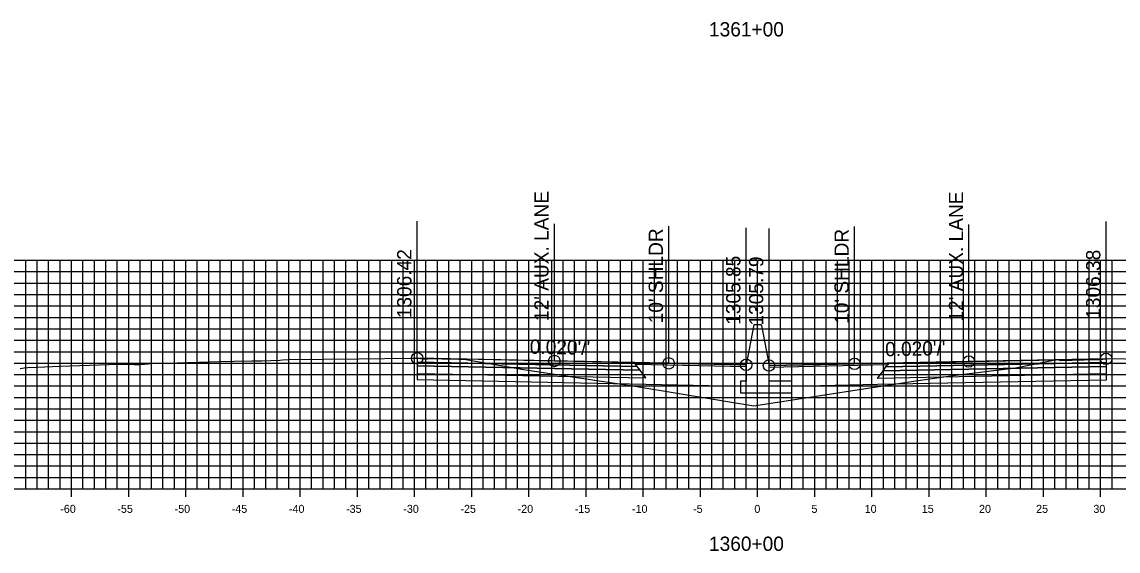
# Model space of a CAD drawing. Extents: x 674939 to 678919, y 750652 to 765176.
# Drawn here: x 678674.2 to 678770.1, y 753977.1 to 754023.4 of the extents above; entities that cross this region are included whole.
import ezdxf

# ---------------------------------------------------------------- set-up
doc = ezdxf.new("R2010")
doc.units = 0
for name, color, linetype in [('Level 10', 7, 'Continuous'), ('Level 17', 7, 'Continuous'), ('Level 18', 7, 'Continuous'), ('Level 19', 7, 'Continuous'), ('Level 20', 7, 'Continuous'), ('Level 22', 7, 'Continuous'), ('Level 23', 7, 'Continuous'), ('Level 4', 7, 'Continuous'), ('Level 8', 7, 'Continuous'), ('Level 9', 7, 'Continuous')]:
    doc.layers.add(name, color=color, linetype=linetype)

msp = doc.modelspace()

# ---------------------------------------------------------------- linework, layer by layer
at = {"layer": 'Level 10'}
msp.add_lwpolyline([(678674.048, 753993.082), (678674.392, 753993.137), (678674.701, 753993.177), (678675.43, 753993.209), (678676.214, 753993.236), (678677.547, 753993.284), (678681.802, 753993.422), (678682.901, 753993.454), (678683.995, 753993.442), (678684.544, 753993.442), (678684.738, 753993.453), (678684.916, 753993.47), (678685.224, 753993.499), (678685.501, 753993.514), (678687.776, 753993.582), (678691.544, 753993.697), (678692.721, 753993.721), (678694.301, 753993.748), (678695.165, 753993.763), (678696.744, 753993.803), (678696.98, 753993.832), (678697.466, 753993.867), (678703.662, 753993.928), (678708.193, 753993.977), (678708.761, 753993.972), (678708.783, 753993.972), (678708.944, 753993.971), (678709.066, 753993.953), (678709.302, 753993.937), (678709.666, 753993.938), (678710.152, 753993.94), (678710.937, 753993.931), (678712.395, 753993.886), (678713.023, 753993.859), (678716.762, 753993.212), (678718.065, 753992.991), (678720.408, 753992.641), (678727.622, 753991.562), (678731.844, 753990.867), (678738.197, 753989.808), (678747.411, 753991.235), (678752.377, 753992.004), (678755.648, 753992.452), (678761.101, 753993.139), (678764.554, 753993.825), (678764.78, 753993.867), (678764.858, 753993.826), (678764.862, 753993.824), (678765.055, 753993.766), (678765.09, 753993.767), (678767.021, 753993.84), (678767.062, 753993.841), (678767.082, 753993.841), (678768.435, 753993.875), (678768.476, 753993.877), (678769.007, 753993.925), (678769.012, 753993.926), (678769.014, 753993.926), (678769.255, 753993.948), (678773.508, 753993.866)], dxfattribs=at)
at = {"layer": 'Level 17'}
for points in [[(678738.203, 753996.896), (678737.533, 753993.396)], [(678738.863, 753996.836), (678738.863, 753996.896), (678738.203, 753996.896), (678738.203, 753996.896)], [(678738.863, 753996.836), (678739.533, 753993.336)], [(678737.533, 753993.396), (678737.533, 753991.961), (678737.033, 753991.961), (678737.033, 753990.961), (678741.533, 753990.961), (678741.533, 753991.961), (678739.533, 753991.961), (678739.533, 753993.336)]]:
    msp.add_lwpolyline(points, dxfattribs=at)
at = {"layer": 'Level 18'}
for points in [[(678737.533, 753993.396), (678730.761, 753993.532), (678720.761, 753993.732), (678708.761, 753993.972)], [(678769.012, 753993.926), (678757.012, 753993.686), (678747.012, 753993.486), (678739.533, 753993.336)]]:
    msp.add_lwpolyline(points, dxfattribs=at)
for points in [[(678708.761, 753993.972), (678708.761, 753993.642), (678728.011, 753993.257), (678727.761, 753993.592)], [(678769.012, 753993.926), (678769.012, 753993.596), (678749.762, 753993.211), (678750.012, 753993.546)], [(678727.761, 753993.592), (678737.533, 753993.396), (678737.537, 753993.239), (678727.88, 753993.432)], [(678749.893, 753993.386), (678739.533, 753993.179), (678739.533, 753993.336), (678750.012, 753993.546)]]:
    msp.add_lwpolyline(points, close=True, dxfattribs=at)
at = {"layer": 'Level 19'}
for points in [[(678708.761, 753993.642), (678708.761, 753993.312), (678728.261, 753992.922), (678728.011, 753993.257)], [(678769.012, 753993.596), (678769.012, 753993.266), (678749.512, 753992.876), (678749.762, 753993.211)], [(678708.761, 753993.312), (678708.761, 753992.652), (678728.761, 753992.252), (678728.261, 753992.922)], [(678769.012, 753993.266), (678769.012, 753992.606), (678749.012, 753992.206), (678749.512, 753992.876)]]:
    msp.add_lwpolyline(points, close=True, dxfattribs=at)
for points in [[(678708.761, 753992.652), (678708.761, 753992.112), (678728.761, 753991.712), (678737.033, 753991.546)], [(678769.012, 753992.606), (678769.012, 753992.066), (678749.012, 753991.666), (678741.533, 753991.516)]]:
    msp.add_lwpolyline(points, dxfattribs=at)
at = {"layer": 'Level 20'}
for p, q in [((678638.533, 754002.551), (678838.533, 754002.551)), ((678674.533, 753982.551), (678674.533, 754002.551)), ((678675.533, 753982.551), (678675.533, 754002.551)), ((678676.533, 753982.551), (678676.533, 754002.551)), ((678677.533, 753982.551), (678677.533, 754002.551)), ((678678.533, 753982.551), (678678.533, 754002.551)), ((678679.533, 753982.551), (678679.533, 754002.551)), ((678680.533, 753982.551), (678680.533, 754002.551)), ((678681.533, 753982.551), (678681.533, 754002.551)), ((678682.533, 753982.551), (678682.533, 754002.551)), ((678683.533, 753982.551), (678683.533, 754002.551)), ((678684.533, 753982.551), (678684.533, 754002.551)), ((678685.533, 753982.551), (678685.533, 754002.551)), ((678686.533, 753982.551), (678686.533, 754002.551)), ((678687.533, 753982.551), (678687.533, 754002.551)), ((678688.533, 753982.551), (678688.533, 754002.551)), ((678689.533, 753982.551), (678689.533, 754002.551)), ((678690.533, 753982.551), (678690.533, 754002.551)), ((678691.533, 753982.551), (678691.533, 754002.551)), ((678692.533, 753982.551), (678692.533, 754002.551)), ((678693.533, 753982.551), (678693.533, 754002.551)), ((678694.533, 753982.551), (678694.533, 754002.551)), ((678695.533, 753982.551), (678695.533, 754002.551)), ((678696.533, 753982.551), (678696.533, 754002.551)), ((678697.533, 753982.551), (678697.533, 754002.551)), ((678698.533, 753982.551), (678698.533, 754002.551)), ((678699.533, 753982.551), (678699.533, 754002.551)), ((678700.533, 753982.551), (678700.533, 754002.551)), ((678701.533, 753982.551), (678701.533, 754002.551)), ((678702.533, 753982.551), (678702.533, 754002.551)), ((678703.533, 753982.551), (678703.533, 754002.551)), ((678704.533, 753982.551), (678704.533, 754002.551)), ((678705.533, 753982.551), (678705.533, 754002.551)), ((678706.533, 753982.551), (678706.533, 754002.551)), ((678707.533, 753982.551), (678707.533, 754002.551)), ((678708.533, 753982.551), (678708.533, 754002.551)), ((678709.533, 753982.551), (678709.533, 754002.551)), ((678710.533, 753982.551), (678710.533, 754002.551)), ((678711.533, 753982.551), (678711.533, 754002.551)), ((678712.533, 753982.551), (678712.533, 754002.551)), ((678713.533, 753982.551), (678713.533, 754002.551)), ((678714.533, 753982.551), (678714.533, 754002.551)), ((678715.533, 753982.551), (678715.533, 754002.551)), ((678716.533, 753982.551), (678716.533, 754002.551)), ((678717.533, 753982.551), (678717.533, 754002.551)), ((678718.533, 753982.551), (678718.533, 754002.551)), ((678719.533, 753982.551), (678719.533, 754002.551)), ((678720.533, 753982.551), (678720.533, 754002.551)), ((678721.533, 753982.551), (678721.533, 754002.551)), ((678722.533, 753982.551), (678722.533, 754002.551)), ((678723.533, 753982.551), (678723.533, 754002.551)), ((678724.533, 753982.551), (678724.533, 754002.551)), ((678725.533, 753982.551), (678725.533, 754002.551)), ((678726.533, 753982.551), (678726.533, 754002.551)), ((678727.533, 753982.551), (678727.533, 754002.551)), ((678728.533, 753982.551), (678728.533, 754002.551)), ((678729.533, 753982.551), (678729.533, 754002.551)), ((678730.533, 753982.551), (678730.533, 754002.551)), ((678731.533, 753982.551), (678731.533, 754002.551)), ((678732.533, 753982.551), (678732.533, 754002.551)), ((678733.533, 753982.551), (678733.533, 754002.551)), ((678734.533, 753982.551), (678734.533, 754002.551)), ((678735.533, 753982.551), (678735.533, 754002.551)), ((678736.533, 753982.551), (678736.533, 754002.551)), ((678737.533, 753982.551), (678737.533, 754002.551)), ((678738.533, 753982.551), (678738.533, 754002.551)), ((678739.533, 753982.551), (678739.533, 754002.551)), ((678740.533, 753982.551), (678740.533, 754002.551)), ((678741.533, 753982.551), (678741.533, 754002.551)), ((678742.533, 753982.551), (678742.533, 754002.551)), ((678743.533, 753982.551), (678743.533, 754002.551)), ((678744.533, 753982.551), (678744.533, 754002.551)), ((678745.533, 753982.551), (678745.533, 754002.551)), ((678746.533, 753982.551), (678746.533, 754002.551)), ((678747.533, 753982.551), (678747.533, 754002.551)), ((678748.533, 753982.551), (678748.533, 754002.551)), ((678749.533, 753982.551), (678749.533, 754002.551)), ((678750.533, 753982.551), (678750.533, 754002.551)), ((678751.533, 753982.551), (678751.533, 754002.551)), ((678752.533, 753982.551), (678752.533, 754002.551)), ((678753.533, 753982.551), (678753.533, 754002.551)), ((678754.533, 753982.551), (678754.533, 754002.551)), ((678755.533, 753982.551), (678755.533, 754002.551)), ((678756.533, 753982.551), (678756.533, 754002.551)), ((678757.533, 753982.551), (678757.533, 754002.551)), ((678758.533, 753982.551), (678758.533, 754002.551)), ((678759.533, 753982.551), (678759.533, 754002.551)), ((678760.533, 753982.551), (678760.533, 754002.551)), ((678761.533, 753982.551), (678761.533, 754002.551)), ((678762.533, 753982.551), (678762.533, 754002.551)), ((678763.533, 753982.551), (678763.533, 754002.551)), ((678764.533, 753982.551), (678764.533, 754002.551)), ((678765.533, 753982.551), (678765.533, 754002.551)), ((678766.533, 753982.551), (678766.533, 754002.551)), ((678767.533, 753982.551), (678767.533, 754002.551)), ((678768.533, 753982.551), (678768.533, 754002.551)), ((678769.533, 753982.551), (678769.533, 754002.551)), ((678638.533, 754001.551), (678838.533, 754001.551)), ((678638.533, 754000.551), (678838.533, 754000.551)), ((678638.533, 753999.551), (678838.533, 753999.551)), ((678638.533, 753998.551), (678838.533, 753998.551)), ((678638.533, 753997.551), (678838.533, 753997.551)), ((678638.533, 753996.551), (678838.533, 753996.551)), ((678638.533, 753995.551), (678838.533, 753995.551)), ((678638.533, 753994.551), (678838.533, 753994.551)), ((678638.533, 753993.551), (678838.533, 753993.551)), ((678638.533, 753992.551), (678838.533, 753992.551)), ((678638.533, 753991.551), (678838.533, 753991.551)), ((678638.533, 753990.551), (678838.533, 753990.551)), ((678638.533, 753989.551), (678838.533, 753989.551)), ((678638.533, 753988.551), (678838.533, 753988.551)), ((678638.533, 753987.551), (678838.533, 753987.551)), ((678638.533, 753986.551), (678838.533, 753986.551)), ((678638.533, 753985.551), (678838.533, 753985.551)), ((678638.533, 753984.551), (678838.533, 753984.551)), ((678638.533, 753983.551), (678838.533, 753983.551)), ((678638.533, 753982.551), (678838.533, 753982.551))]:
    msp.add_line(p, q, dxfattribs=at)
at = {"layer": 'Level 23'}
for p, q in [((678708.761, 753993.972), (678708.761, 754005.972)), ((678720.761, 753993.732), (678720.761, 754005.732)), ((678730.761, 753993.532), (678730.761, 754005.532)), ((678737.533, 753993.396), (678737.533, 754005.396)), ((678739.533, 753993.336), (678739.533, 754005.336)), ((678747.012, 753993.486), (678747.012, 754005.486)), ((678757.012, 753993.686), (678757.012, 754005.686)), ((678769.012, 753993.926), (678769.012, 754005.926))]:
    msp.add_line(p, q, dxfattribs=at)
at = {"layer": 'Level 4'}
for centre in [(678708.761, 753993.972), (678720.761, 753993.732), (678730.761, 753993.532), (678737.533, 753993.396), (678739.533, 753993.336), (678747.012, 753993.486), (678757.012, 753993.686), (678769.012, 753993.926)]:
    msp.add_circle(centre, 0.5, dxfattribs=at)
at = {"layer": 'Level 8'}
for p, q in [((678678.533, 753981.851), (678678.533, 753983.251)), ((678683.533, 753981.851), (678683.533, 753983.251)), ((678688.533, 753981.851), (678688.533, 753983.251)), ((678693.533, 753981.851), (678693.533, 753983.251)), ((678698.533, 753981.851), (678698.533, 753983.251)), ((678703.533, 753981.851), (678703.533, 753983.251)), ((678708.533, 753981.851), (678708.533, 753983.251)), ((678713.533, 753981.851), (678713.533, 753983.251)), ((678718.533, 753981.851), (678718.533, 753983.251)), ((678723.533, 753981.851), (678723.533, 753983.251)), ((678728.533, 753981.851), (678728.533, 753983.251)), ((678733.533, 753981.851), (678733.533, 753983.251)), ((678738.533, 753981.851), (678738.533, 753983.251)), ((678743.533, 753981.851), (678743.533, 753983.251)), ((678748.533, 753981.851), (678748.533, 753983.251)), ((678753.533, 753981.851), (678753.533, 753983.251)), ((678758.533, 753981.851), (678758.533, 753983.251)), ((678763.533, 753981.851), (678763.533, 753983.251)), ((678768.533, 753981.851), (678768.533, 753983.251)), ((678638.533, 753982.551), (678838.533, 753982.551))]:
    msp.add_line(p, q, dxfattribs=at)

# ---------------------------------------------------------------- texts
at = {"layer": 'Level 22'}
for rotation, p in [(358.85424, (678718.597, 753994.375)), (1.14576, (678749.699, 753994.14))]:
    msp.add_text("0.020'/'", height=1.25, rotation=rotation, dxfattribs=at).set_placement(p)
at = {"layer": 'Level 23'}
for s, p in [("12' AUX. LANE", (678720.261, 753997.232)), ("12' AUX. LANE", (678756.512, 753997.186)), ("10' SHLDR", (678730.261, 753997.032)), ("10' SHLDR", (678746.512, 753996.986)), ('1306.42', (678708.261, 753997.472)), ('1306.38', (678768.512, 753997.426)), ('1305.85', (678737.033, 753996.896)), ('1305.79', (678739.033, 753996.836))]:
    msp.add_text(s, height=1.25, rotation=90, dxfattribs=at).set_placement(p)
at = {"layer": 'Level 9'}
for s, height, p in [('1361+00', 1.25, (678734.282, 754022.126)), ('-60', 0.7, (678677.552, 753980.451)), ('-55', 0.7, (678682.546, 753980.451)), ('-50', 0.7, (678687.552, 753980.451)), ('-45', 0.7, (678692.546, 753980.451)), ('-40', 0.7, (678697.552, 753980.451)), ('-35', 0.7, (678702.546, 753980.451)), ('-30', 0.7, (678707.552, 753980.451)), ('-25', 0.7, (678712.546, 753980.451)), ('-20', 0.7, (678717.552, 753980.451)), ('-15', 0.7, (678722.546, 753980.451)), ('-10', 0.7, (678727.552, 753980.451)), ('-5', 0.7, (678732.896, 753980.451)), ('0', 0.7, (678738.252, 753980.451)), ('5', 0.7, (678743.246, 753980.451)), ('10', 0.7, (678747.902, 753980.451)), ('15', 0.7, (678752.896, 753980.451)), ('20', 0.7, (678757.902, 753980.451)), ('25', 0.7, (678762.896, 753980.451)), ('30', 0.7, (678767.902, 753980.451)), ('1360+00', 1.25, (678734.282, 753977.126))]:
    msp.add_text(s, height=height, dxfattribs=at).set_placement(p)

doc.saveas('drawing.dxf')
